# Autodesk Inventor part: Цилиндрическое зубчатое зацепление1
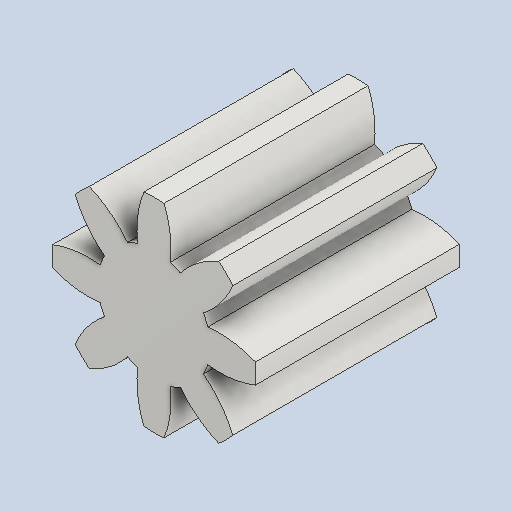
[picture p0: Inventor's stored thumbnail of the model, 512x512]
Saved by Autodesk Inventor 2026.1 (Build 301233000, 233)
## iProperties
Created: 2026-02
Part Number: Цилиндрическое зубчатое зацепление1
Material: Steel
Document SubType Name: Modeling
Designer: Yury Melnikov
Categories: <?xml version="1.0" encoding="UTF-16"?> <MemberInstance><Categories><FamilyTemplate><FamilyTemplateParameter ValueType="xs:double" Id="1" ObjectReferenceKey="da
Density: 1 g/cm^3
Appearance: Steel
CustomPartVersion: 1
Author: Yury Melnikov
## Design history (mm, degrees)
sketch "Sketch1"
  geometry: C1 r 10 at (0, 0)
  constraints: 1 centre point
  dimensions: "d0" = 20 diameter of C1 (= da_da)
extrude "Extrusion1" new body sketch "Sketch1" distance "d1" = 20 (= da_b); taper "d2" = 0 deg
workplane "Work Plane2"
feature "Средний диаметр" dims "d4" = 10, "d5" = 0
workplane "Work Plane8"
workplane "Work Plane9"
feature "Цилиндрическое зубчатое зацепление" dims "da_b" = 20, "da_d" = 16, "da_aw" = 16, "da_da" = 20, "da_df" = 11, "da_dw" = 16, angle "da_beta" = 0 deg, "da_lefttooth" = 0, "da_righttooth" = 0
body "Solid1"
sketch "Sketch2"
  geometry: C1 r 10 at (0, 0) reference; C2 r 8 at (0, 0)
  constraints: 1 centre point, 1 coincident
  dimensions: "d3" = 16 diameter of C2 (= da_d)
body "Srf1"
other parameters: "d16" = 16 (= da_aw), "d17" = 0, "d34" = 22.5 deg (computed from da_z), "d39" = 0, "d41" = 0, "d43" = 16 (= da_aw), "d46" = 16 (= da_aw), "d47" = 0, "d48" = 0
